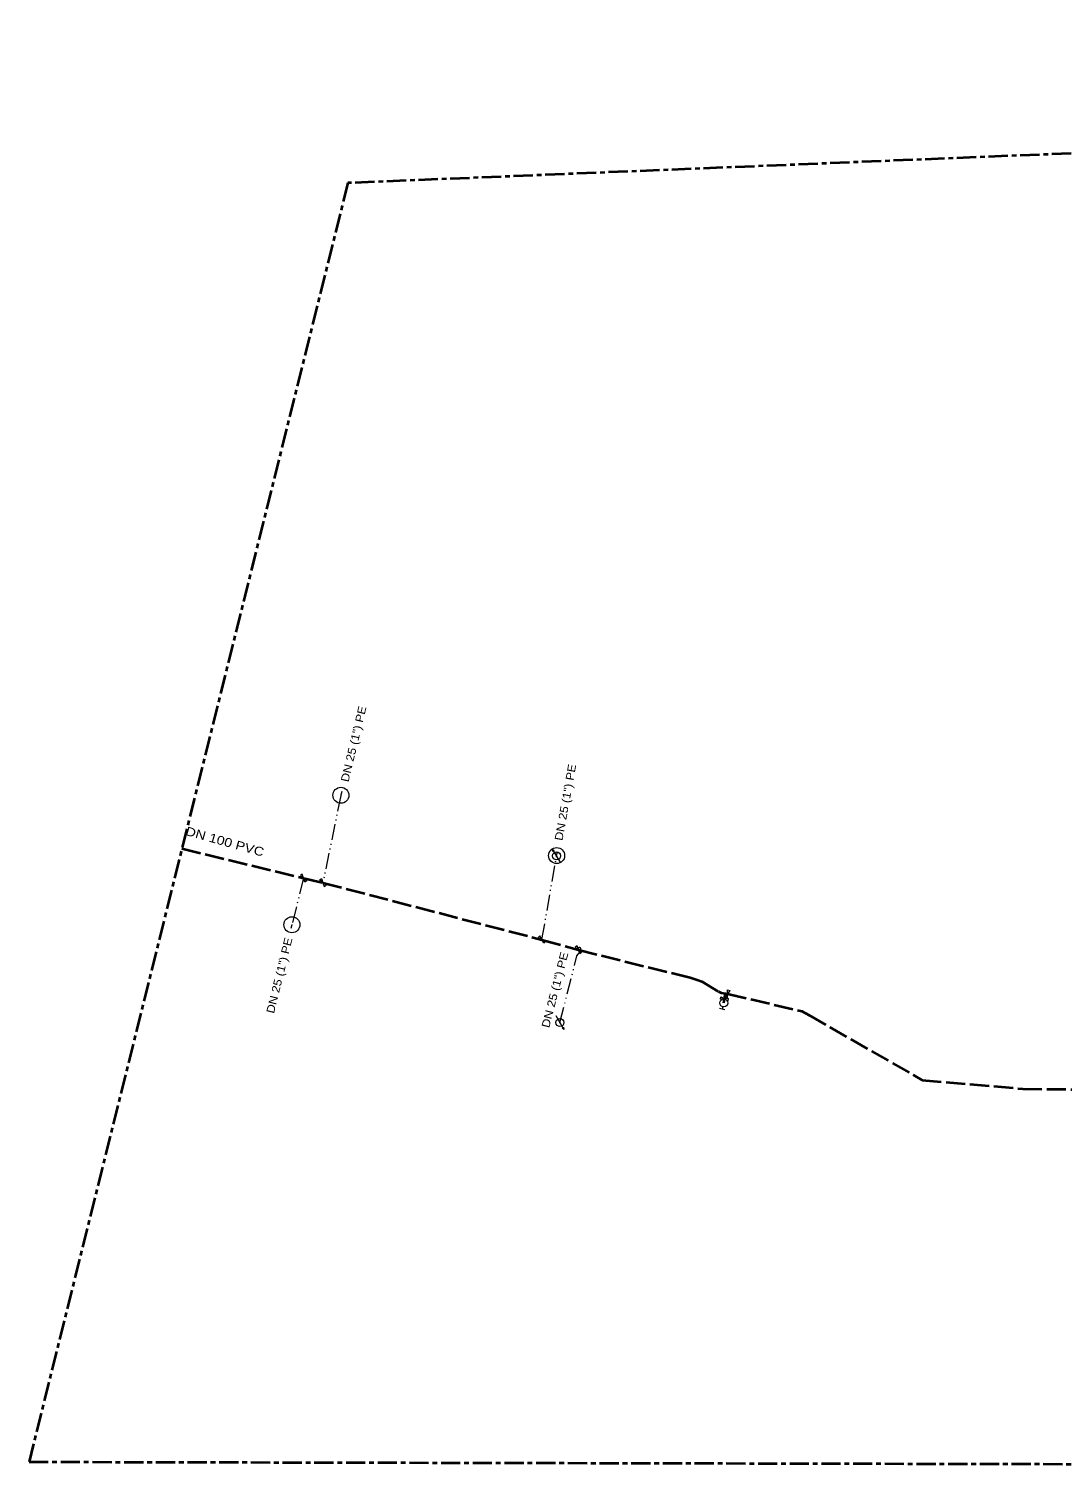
# Model space of a CAD drawing. Extents: x -666789 to -665748, y -1041871 to -1041144.
# Drawn here: x -666788.7 to -666659.5, y -1041326.1 to -1041144.5 of the extents above; entities that cross this region are included whole.
import ezdxf
from ezdxf.enums import TextEntityAlignment as Align

# ---------------------------------------------------------------- set-up
doc = ezdxf.new("R2010")
doc.units = 0
doc.header["$LTSCALE"] = 0.4
for name, pattern in [('DASH_DOUBLE_DOT', [9.2, 5, -1.2, 0.3, -1.2, 0.3, -1.2]), ('LONG_DASH_SHORT_DASH', [9.9, 6, -1.2, 1.5, -1.2]), ('LONG_DASHED', [7.5, 6, -1.5])]:
    doc.linetypes.add(name, pattern=pattern)
for name, color, linetype, lineweight in [('10', 7, 'Continuous', 13), ('12', 7, 'Continuous', 13), ('21', 7, 'LONG_DASHED', 35), ('32', 7, 'DASH_DOUBLE_DOT', 13), ('63', 7, 'LONG_DASH_SHORT_DASH', 35)]:
    doc.layers.add(name, color=color, linetype=linetype, lineweight=lineweight)
doc.layers.add('29', color=7, linetype='Continuous')
doc.layers.add('39', color=7, linetype='Continuous')

msp = doc.modelspace()

# ---------------------------------------------------------------- linework, layer by layer
at = {"layer": '10'}
for p, q in [((-666701.785, -1041267.022), (-666702.462, -1041266.845)), ((-666702.048, -1041266.643), (-666702.123, -1041266.933))]:
    msp.add_line(p, q, dxfattribs=at)
for points in [[(-666754.828, -1041250.261), (-666754.02, -1041250.923), (-666754.269, -1041251.09), (-666754.58, -1041250.094)], [(-666751.595, -1041251.444), (-666752.417, -1041250.799), (-666752.171, -1041250.626), (-666751.841, -1041251.617)], [(-666725.099, -1041257.977), (-666724.187, -1041258.487), (-666724.403, -1041258.695), (-666724.883, -1041257.769)], [(-666720.499, -1041259.2), (-666719.677, -1041259.844), (-666719.922, -1041260.017), (-666720.254, -1041259.027)], [(-666701.309, -1041265.599), (-666702.35, -1041265.682), (-666702.287, -1041265.388), (-666701.373, -1041265.893)], [(-666701.474, -1041265.562), (-666701.465, -1041264.518), (-666701.179, -1041264.607), (-666701.761, -1041265.474)]]:
    msp.add_lwpolyline(points, close=True, dxfattribs=at)
for centre, radius in [((-666749.7638, -1041240.2212), 1), ((-666722.8035, -1041247.7559), 1), ((-666755.8818, -1041256.3897), 1), ((-666701.9195, -1041266.1594), 0.5)]:
    msp.add_circle(centre, radius, dxfattribs=at)
at = {"layer": '12'}
for p, q in [((-666722.286, -1041248.641), (-666723.332, -1041246.936)), ((-666722.904, -1041267.749), (-666721.885, -1041269.471))]:
    msp.add_line(p, q, dxfattribs=at)
for points in [[(-666723.273, -1041247.23), (-666723.332, -1041246.936), (-666723.097, -1041247.122)], [(-666721.94, -1041269.176), (-666721.885, -1041269.471), (-666722.117, -1041269.281)]]:
    msp.add_lwpolyline(points, dxfattribs=at)
for centre in [(-666722.81, -1041247.7882), (-666722.3938, -1041268.6106)]:
    msp.add_circle(centre, 0.5, dxfattribs=at)
at = {"layer": '21'}
for p, q in [((-666769.62, -1041246.876), (-666754.42, -1041250.57)), ((-666754.42, -1041250.57), (-666752.01, -1041251.14)), ((-666752.01, -1041251.14), (-666724.65, -1041258.27)), ((-666724.65, -1041258.27), (-666720.09, -1041259.53)), ((-666701.92, -1041266.16), (-666701.83, -1041265.64)), ((-666701.83, -1041265.64), (-666701.714, -1041264.984)), ((-666701.714, -1041264.986), (-666701.47, -1041265.04))]:
    msp.add_line(p, q, dxfattribs=at)
for points in [[(-666720.09, -1041259.53), (-666706.128, -1041262.997), (-666705.11, -1041263.336), (-666704.66, -1041263.498), (-666702.581, -1041264.751), (-666702.254, -1041264.882), (-666701.714, -1041264.986)], [(-666701.47, -1041265.04), (-666692.184, -1041267.175), (-666691.261, -1041267.708), (-666677.133, -1041275.8), (-666664.563, -1041276.888), (-666644.556, -1041277.136), (-666615.923, -1041277.115), (-666590.103, -1041276.381), (-666565.432, -1041275.465), (-666553.635, -1041274.964), (-666500.513, -1041272.709), (-666489.02, -1041272.154), (-666489.02, -1041272.154)]]:
    msp.add_lwpolyline(points, dxfattribs=at)
at = {"layer": '32'}
for p, q in [((-666749.769, -1041240.241), (-666752.006, -1041251.121)), ((-666722.804, -1041247.756), (-666722.714, -1041247.264)), ((-666724.643, -1041258.232), (-666722.81, -1041247.788)), ((-666722.81, -1041247.788), (-666722.804, -1041247.756)), ((-666754.425, -1041250.592), (-666755.878, -1041256.374)), ((-666754.42, -1041250.57), (-666754.425, -1041250.592)), ((-666752.006, -1041251.121), (-666752.01, -1041251.14)), ((-666755.882, -1041256.39), (-666756.002, -1041256.875)), ((-666755.878, -1041256.374), (-666755.882, -1041256.39)), ((-666724.65, -1041258.27), (-666724.643, -1041258.232)), ((-666722.418, -1041268.706), (-666722.394, -1041268.611))]:
    msp.add_line(p, q, dxfattribs=at)
for points in [[(-666749.647, -1041239.735), (-666749.764, -1041240.221), (-666749.769, -1041240.241)], [(-666722.394, -1041268.611), (-666720.26, -1041260.291), (-666720.114, -1041260.058), (-666719.839, -1041259.717), (-666719.774, -1041259.533), (-666719.79, -1041259.377), (-666719.838, -1041259.29), (-666719.926, -1041259.244), (-666719.997, -1041259.245), (-666720.062, -1041259.292), (-666720.088, -1041259.522), (-666720.09, -1041259.53)]]:
    msp.add_lwpolyline(points, dxfattribs=at)
at = {"layer": '63'}
msp.add_lwpolyline([(-666748.889, -1041163.712), (-666788.722, -1041323.504), (-666347.808, -1041324.419), (-666242.501, -1041491.536), (-666296.986, -1041679.715), (-666241.127, -1041826.687), (-665982.439, -1041871.099), (-665998.006, -1041671.474), (-665765.873, -1041672.389), (-665748.475, -1041456.282), (-665860.192, -1041368.831), (-666182.98, -1041263.982), (-666278.671, -1041144.482)], close=True, dxfattribs=at)

# ---------------------------------------------------------------- texts
at = {"layer": '29', "width": 1.2}
msp.add_text('DN 100 PVC', height=1.1, rotation=344.349, dxfattribs=at).set_placement((-666764.4024, -1041246.527), align=Align.CENTER)
at = {"layer": '39', "width": 1.15}
for rotation, p in [(76.495, (-666747.688, -1041233.9198)), (79.69, (-666721.2186, -1041241.1835)), (76.084, (-666756.9642, -1041262.8412)), (75.614, (-666722.5353, -1041264.6542))]:
    msp.add_text('DN 25 (1") PE', height=1, rotation=rotation, dxfattribs=at).set_placement(p, align=Align.CENTER)

doc.saveas('drawing.dxf')
